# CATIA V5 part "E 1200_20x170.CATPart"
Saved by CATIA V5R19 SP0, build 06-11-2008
Definition: E 1200_20x170
Nomenclature: E 1200_20x170
Description: PART--DESC
Material "Steel": density 7860 kg/m3, Young's modulus 2e+11 Pa, Poisson ratio 0.266, thermal expansion 1.17e-05 1/K
Bounding box of the stored display mesh (mm): x 205 to 235, y -244 to -214, z -322.5 to -132.5
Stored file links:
  G:\UTB\Kombinované\Bakalářská práce\Catia\FORMA\E 1200_20x170.CATPart
  D:\Aplikace\CATIA\Nová složka\win_b64\startup\materials\Catalog.CATMaterial
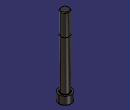
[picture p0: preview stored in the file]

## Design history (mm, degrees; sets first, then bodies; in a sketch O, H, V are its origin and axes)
Body1 "E 1200_20x170" (main body)
  Solid1: solid without history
